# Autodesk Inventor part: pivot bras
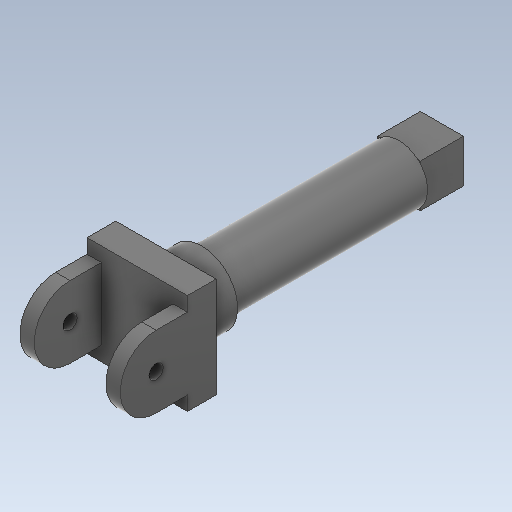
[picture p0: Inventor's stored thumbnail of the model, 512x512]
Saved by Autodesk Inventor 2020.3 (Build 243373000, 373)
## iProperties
Created: 2020-09
Part Number: pivot bras
Material: Plastique ABS
Document SubType Name: Modeling
Designer: ficho
Density: 1.06 g/cm^3
Appearance: Lisse - Noir
Mass: 3.25909 g
Surface Area: 20.4947 cm^2
Volume: 3.07462 cm^3
Author: ficho
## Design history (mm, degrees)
sketch "Esquisse1"
  geometry: L1 (-7, -7)-(7, -7); L2 (7, -7)-(7, 7); L3 (7, 7)-(-7, 7); L4 (-7, 7)-(-7, -7); 1 further point
  constraints: 8 end point, 2 parallel, 1 horizontal, 1 perpendicular
  dimensions: "d0" = 7 distance from line of L2 point (0, 0); "d1" = 14 distance between parallel lines of L2 L4 (= 2 x d0); "d2" = 7 distance from line of point (0, 0) L3 (= d0); "d3" = 14 distance between parallel lines of L1 L3 (= d1)
extrude "Extrusion1" new body sketch "Esquisse1" distance "d4" = 14; taper "d5" = 0 deg
sketch "Esquisse2"
  geometry: L1 (14, -14)-(0, -14) reference; L2 (2, -14)-(12, -14); L3 (12, -14)-(12, -4); L4 (12, -4)-(2, -4); L5 (2, -4)-(2, -14); L6 (0, 0)-(0, -14) reference; L7 (14, 0)-(14, -14) reference; 2 further points
  constraints: 8 end point, 2 parallel, 1 horizontal, 1 perpendicular, 1 point on line
  dimensions: "d6" = 4 distance from line of point (7, 0) L4; "d7" = 2 distance between parallel lines of L5 L6; "d8" = 2 distance between parallel lines of L7 L3 (= d7)
extrude "Extrusion2" cut sketch "Esquisse2" extent not by distance; stored distance "d9" = 0; taper "d10" = 0 deg
sketch "Esquisse3"
  geometry: L1 (5.629, -2)-(10, -2); L2 (5.629, -12)-(10, -12); L3 (14, 0)-(14, -14) reference; L4 (14, -14)-(0, -14) reference; L5 (0, 0)-(0, -14) reference; L6 (14, 0)-(0, 0) reference; L7 (10, -14)-(0, -14) reference; L8 (10, 0)-(10, -14) reference; L9 (0, 0)-(10, 0) reference; L10 (0, -14)-(0, 0) reference; L11 (10, -2)-(10, 1.922); L12 (10, 1.922)-(-7.897, 1.922); L13 (-7.897, 1.922)-(-8.381, -18.071); L14 (-8.381, -18.071)-(10, -18.517); L15 (10, -18.517)-(10.158, -12.002); A1 r 5 centre (5.629, -7) between (5.629, -2) and (5.629, -12); 4 further points
  constraints: 14 end point, 3 perpendicular, 3 point on line, 2 horizontal, 2 point on circle, 2 tangent, 1 centre point, 1 vertical
  dimensions: "d11" = 10 diameter of A1
extrude "Extrusion3" cut sketch "Esquisse3" extent not by distance; stored distance "d12" = 12; taper "d13" = 0 deg
sketch "Esquisse4"
  geometry: C1 r 1 at (-8.371, 7); A1 r 5 centre (-8.371, 7) between (-8.371, 12) and (-8.371, 2) reference; 1 further point
  constraints: 1 centre point, 1 coincident
  dimensions: "d14" = 2 diameter of C1
extrude "Extrusion4" cut sketch "Esquisse4" extent not by distance; stored distance "d15" = 0; taper "d16" = 0 deg
sketch "Esquisse5"
  geometry: L1 (5, 0)-(-5, 0); L2 (-5, 0)-(-5, -5); L3 (-5, -5)-(-4, -5); L4 (-4, -5)-(-4, -32.5); L5 (-4, -32.5)-(0, -32.5); L6 (7, 0)-(-7, 0) reference; L7 (0, 0)-(0, -32.5); 1 further point
  constraints: 12 end point, 1 collinear, 1 horizontal, 1 parallel, 1 perpendicular
  dimensions: "d18" = 5 distance from line of L2 L7.start; "d19" = 5 distance between parallel lines of L3 L1; "d22" = 27.5 distance between parallel lines of L5 L3
revolve "Révolution1" sketch "Esquisse5" stored, may be unused: angle "d23" = 90 deg
sketch "Esquisse6"
  geometry: L1 (-3, 3)-(3, 3); L2 (3, 3)-(3, -3); L3 (3, -3)-(-3, -3); L4 (-3, -3)-(-3, 3); 1 further point
  constraints: 8 end point, 2 parallel, 1 horizontal, 1 perpendicular
  dimensions: "d24" = 3 distance from line of point (0, 0) L4; "d25" = 6 distance between parallel lines of L4 L2 (= 2 x d24); "d26" = 3 distance from line of L1 point (0, 0) (= d24); "d27" = 6 distance between parallel lines of L1 L3 (= d25)
extrude "Extrusion5" join sketch "Esquisse6" distance "d28" = 6; taper "d29" = 0 deg
sketch "Esquisse7"
  geometry: 1 further point
hole "Perçage1" sketch "Esquisse7" at (0, 0) diameter "d30" = 2.013; stored, may be unused: countersink angle "d34" = 90 deg, drill point angle "d36" = 118 deg; dims "d31" = 5, "d32" = 4, "d33" = 2, "d35" = 6
node "Solide1"
node "Boucle projetée1"
node "Boucle projetée2"
